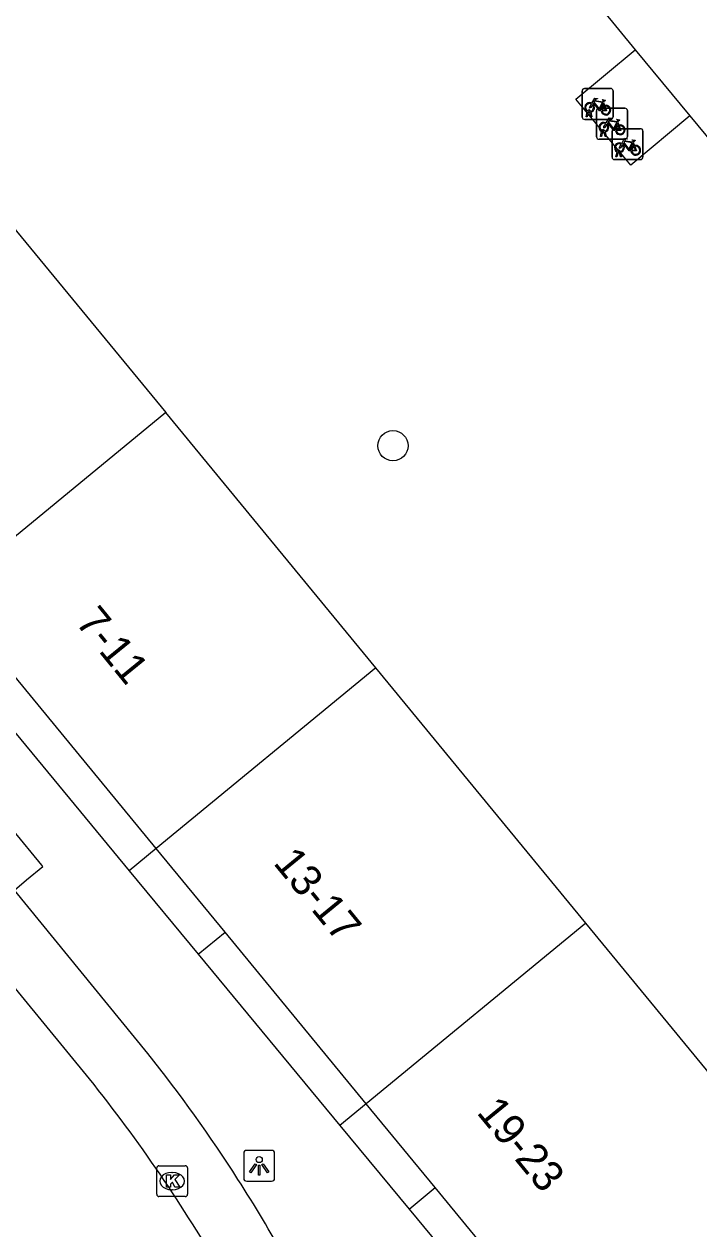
# Model space of a CAD drawing. Extents: x 162347 to 162868, y 381221 to 381813.
# Drawn here: x 162450.01 to 162471.84, y 381680.03 to 381719.03 of the extents above; entities that cross this region are included whole.
import ezdxf

# ---------------------------------------------------------------- set-up
doc = ezdxf.new("R2010")
doc.units = 0
for name, color, linetype in [('IMGEO_Boom', 7, 'Continuous'), ('IMGEO_Fietsenrek', 7, 'Continuous'), ('IMGEO_Kolk', 7, 'Continuous'), ('IMGEO_Lichtpunt', 7, 'Continuous'), ('IMGEO_Pand', 7, 'Continuous'), ('IMGEO_Pand_nummerreeks', 7, 'Continuous'), ('IMGEO_Rijbaan_lokaal_open', 7, 'Continuous'), ('IMGEO_Voetpad_open', 7, 'Continuous')]:
    doc.layers.add(name, color=color, linetype=linetype)

msp = doc.modelspace()

# ---------------------------------------------------------------- linework, layer by layer
at = {"layer": 'IMGEO_Boom'}
msp.add_circle((162461.946, 381705.383), 0.489, dxfattribs=at)
at = {"layer": 'IMGEO_Fietsenrek'}
for p, q in [((162468.067, 381716.021), (162468.067, 381716.862)), ((162468.067, 381716.862), (162468.067, 381716.021)), ((162468.142, 381716.946), (162468.983, 381716.946)), ((162468.983, 381716.946), (162468.142, 381716.946)), ((162469.067, 381716.871), (162469.067, 381716.03)), ((162469.067, 381716.03), (162469.067, 381716.871)), ((162468.754, 381716.495), (162468.79, 381716.4)), ((162468.194, 381716.03), (162468.233, 381716.19)), ((162468.263, 381716.178), (162468.228, 381716.03)), ((162468.305, 381716.202), (162468.304, 381716.206)), ((162468.346, 381716.03), (162468.312, 381716.172)), ((162468.336, 381716.213), (162468.337, 381716.206)), ((162468.344, 381716.176), (162468.379, 381716.03)), ((162468.53, 381715.382), (162468.53, 381716.223)), ((162468.53, 381716.223), (162468.53, 381715.382)), ((162468.605, 381716.307), (162469.446, 381716.307)), ((162469.446, 381716.307), (162468.605, 381716.307)), ((162469.53, 381716.232), (162469.53, 381715.391)), ((162469.53, 381715.391), (162469.53, 381716.232)), ((162468.992, 381715.946), (162468.151, 381715.946)), ((162468.151, 381715.946), (162468.992, 381715.946)), ((162468.228, 381716.03), (162468.194, 381716.03)), ((162468.379, 381716.03), (162468.346, 381716.03)), ((162469.217, 381715.856), (162469.253, 381715.761)), ((162469.455, 381715.307), (162468.614, 381715.307)), ((162468.614, 381715.307), (162469.455, 381715.307)), ((162468.657, 381715.391), (162468.696, 381715.551)), ((162468.691, 381715.391), (162468.657, 381715.391)), ((162468.726, 381715.539), (162468.691, 381715.391)), ((162468.768, 381715.563), (162468.767, 381715.567)), ((162468.809, 381715.391), (162468.775, 381715.533)), ((162468.799, 381715.574), (162468.8, 381715.567)), ((162468.807, 381715.537), (162468.842, 381715.391)), ((162468.842, 381715.391), (162468.809, 381715.391)), ((162469.032, 381714.72), (162469.032, 381715.561)), ((162469.032, 381715.561), (162469.032, 381714.72)), ((162469.107, 381715.645), (162469.948, 381715.645)), ((162469.948, 381715.645), (162469.107, 381715.645)), ((162470.032, 381715.57), (162470.032, 381714.729)), ((162470.032, 381714.729), (162470.032, 381715.57)), ((162469.159, 381714.729), (162469.198, 381714.889)), ((162469.228, 381714.877), (162469.193, 381714.729)), ((162469.27, 381714.901), (162469.269, 381714.905)), ((162469.301, 381714.912), (162469.302, 381714.905)), ((162469.719, 381715.194), (162469.755, 381715.099)), ((162469.957, 381714.645), (162469.116, 381714.645)), ((162469.116, 381714.645), (162469.957, 381714.645)), ((162469.193, 381714.729), (162469.159, 381714.729)), ((162469.311, 381714.729), (162469.277, 381714.871)), ((162469.309, 381714.875), (162469.344, 381714.729)), ((162469.344, 381714.729), (162469.311, 381714.729))]:
    msp.add_line(p, q, dxfattribs=at)
for points in [[(162468.401, 381716.42), (162468.349, 381716.33), (162468.309, 381716.305), (162468.31, 381716.352), (162468.365, 381716.446)], [(162468.38, 381716.472), (162468.475, 381716.636), (162468.561, 381716.622), (162468.563, 381716.613), (162468.507, 381716.602), (162468.48, 381716.557), (162468.736, 381716.516)], [(162468.676, 381716.228), (162468.626, 381716.228), (162468.435, 381716.479), (162468.416, 381716.447)], [(162468.723, 381716.491), (162468.466, 381716.532), (162468.449, 381716.503), (162468.616, 381716.283), (162468.723, 381716.491)], [(162468.771, 381716.393), (162468.741, 381716.47), (162468.632, 381716.252), (162468.675, 381716.252)], [(162468.736, 381716.516), (162468.761, 381716.565), (162468.755, 381716.569), (162468.732, 381716.573), (162468.72, 381716.58), (162468.719, 381716.583), (162468.721, 381716.588), (162468.816, 381716.573), (162468.818, 381716.563), (162468.808, 381716.55), (162468.796, 381716.544), (162468.782, 381716.55), (162468.754, 381716.495)], [(162468.705, 381716.252), (162468.825, 381716.251), (162468.781, 381716.365)], [(162468.801, 381716.372), (162468.856, 381716.227), (162468.706, 381716.227)], [(162468.864, 381715.781), (162468.812, 381715.691), (162468.772, 381715.666), (162468.773, 381715.713), (162468.828, 381715.807)], [(162468.843, 381715.833), (162468.938, 381715.997), (162469.024, 381715.983), (162469.026, 381715.974), (162468.97, 381715.963), (162468.943, 381715.918), (162469.199, 381715.877)], [(162469.139, 381715.589), (162469.089, 381715.589), (162468.898, 381715.84), (162468.879, 381715.808)], [(162469.186, 381715.852), (162468.929, 381715.893), (162468.912, 381715.864), (162469.079, 381715.644), (162469.186, 381715.852)], [(162469.234, 381715.754), (162469.204, 381715.831), (162469.095, 381715.613), (162469.138, 381715.613)], [(162469.168, 381715.613), (162469.288, 381715.612), (162469.244, 381715.726)], [(162469.264, 381715.733), (162469.319, 381715.588), (162469.169, 381715.588)], [(162469.199, 381715.877), (162469.224, 381715.926), (162469.218, 381715.93), (162469.195, 381715.934), (162469.183, 381715.941), (162469.182, 381715.944), (162469.184, 381715.949), (162469.279, 381715.934), (162469.281, 381715.924), (162469.271, 381715.911), (162469.259, 381715.905), (162469.245, 381715.911), (162469.217, 381715.856)], [(162469.345, 381715.171), (162469.44, 381715.335), (162469.526, 381715.321), (162469.528, 381715.312), (162469.472, 381715.301), (162469.445, 381715.256), (162469.701, 381715.215)], [(162469.701, 381715.215), (162469.726, 381715.264), (162469.72, 381715.268), (162469.697, 381715.272), (162469.685, 381715.279), (162469.684, 381715.282), (162469.686, 381715.287), (162469.781, 381715.272), (162469.783, 381715.262), (162469.773, 381715.249), (162469.761, 381715.243), (162469.747, 381715.249), (162469.719, 381715.194)], [(162469.366, 381715.119), (162469.314, 381715.029), (162469.274, 381715.004), (162469.275, 381715.051), (162469.33, 381715.145)], [(162469.641, 381714.927), (162469.591, 381714.927), (162469.4, 381715.178), (162469.381, 381715.146)], [(162469.688, 381715.19), (162469.431, 381715.231), (162469.414, 381715.202), (162469.581, 381714.982), (162469.688, 381715.19)], [(162469.736, 381715.092), (162469.706, 381715.169), (162469.597, 381714.951), (162469.64, 381714.951)], [(162469.67, 381714.951), (162469.79, 381714.95), (162469.746, 381715.064)], [(162469.766, 381715.071), (162469.821, 381714.926), (162469.671, 381714.926)]]:
    msp.add_lwpolyline(points, dxfattribs=at)
for centre, radius, start, end in [((162468.145, 381716.868), 0.0779, 92.4484, 184.2845), ((162468.145, 381716.868), 0.0779, 92.4484, 184.2845), ((162468.989, 381716.868), 0.0779, 2.4484, 94.2845), ((162468.989, 381716.868), 0.0779, 2.4484, 94.2845), ((162468.307, 381716.331), 0.159, 62.6766, 242.1369), ((162468.307, 381716.331), 0.129, 63.3192, 238.903), ((162468.307, 381716.331), 0.159, 283.5766, 46.6042), ((162468.287, 381716.202), 0.0499, 12.8025, 158.6934), ((162468.307, 381716.331), 0.159, 253.9967, 271.7867), ((162468.287, 381716.202), 0.0174, 12.8025, 163.4502), ((162468.307, 381716.331), 0.129, 253.415, 269.0204), ((162468.307, 381716.331), 0.129, 283.6043, 43.4302), ((162468.608, 381716.229), 0.0779, 92.4484, 184.2845), ((162468.608, 381716.229), 0.0779, 92.4484, 184.2845), ((162468.834, 381716.247), 0.159, 113.3408, 178.3217), ((162468.834, 381716.247), 0.159, 187.0065, 105.7708), ((162468.834, 381716.247), 0.129, 113.923, 177.9556), ((162468.834, 381716.247), 0.129, 188.6715, 104.5883), ((162469.452, 381716.229), 0.0779, 2.4484, 94.2845), ((162469.452, 381716.229), 0.0779, 2.4484, 94.2845), ((162468.145, 381716.024), 0.0779, 182.4484, 274.2845), ((162468.145, 381716.024), 0.0779, 182.4484, 274.2845), ((162468.77, 381715.692), 0.159, 62.6766, 242.1369), ((162468.77, 381715.692), 0.129, 63.3192, 238.903), ((162468.77, 381715.692), 0.129, 283.6043, 43.4302), ((162468.77, 381715.692), 0.159, 283.5766, 46.6042), ((162468.989, 381716.024), 0.0779, 272.4484, 4.2845), ((162468.989, 381716.024), 0.0779, 272.4484, 4.2845), ((162469.297, 381715.608), 0.159, 113.3408, 178.3217), ((162469.297, 381715.608), 0.159, 187.0065, 105.7708), ((162469.297, 381715.608), 0.129, 113.923, 177.9556), ((162469.297, 381715.608), 0.129, 188.6715, 104.5883), ((162468.608, 381715.385), 0.0779, 182.4484, 274.2845), ((162468.608, 381715.385), 0.0779, 182.4484, 274.2845), ((162468.75, 381715.563), 0.0499, 12.8025, 158.6934), ((162468.77, 381715.692), 0.159, 253.9967, 271.7867), ((162468.75, 381715.563), 0.0174, 12.8025, 163.4502), ((162468.77, 381715.692), 0.129, 253.415, 269.0204), ((162469.11, 381715.567), 0.0779, 92.4484, 184.2845), ((162469.11, 381715.567), 0.0779, 92.4484, 184.2845), ((162469.452, 381715.385), 0.0779, 272.4484, 4.2845), ((162469.452, 381715.385), 0.0779, 272.4484, 4.2845), ((162469.954, 381715.567), 0.0779, 2.4484, 94.2845), ((162469.954, 381715.567), 0.0779, 2.4484, 94.2845), ((162469.272, 381715.03), 0.159, 62.6766, 242.1369), ((162469.272, 381715.03), 0.129, 63.3192, 238.903), ((162469.252, 381714.901), 0.0499, 12.8025, 158.6934), ((162469.272, 381715.03), 0.159, 253.9967, 271.7867), ((162469.252, 381714.901), 0.0174, 12.8025, 163.4502), ((162469.272, 381715.03), 0.129, 253.415, 269.0204), ((162469.272, 381715.03), 0.129, 283.6043, 43.4302), ((162469.272, 381715.03), 0.159, 283.5766, 46.6042), ((162469.799, 381714.946), 0.159, 113.3408, 178.3217), ((162469.799, 381714.946), 0.159, 187.0065, 105.7708), ((162469.799, 381714.946), 0.129, 113.923, 177.9556), ((162469.799, 381714.946), 0.129, 188.6715, 104.5883), ((162469.11, 381714.723), 0.0779, 182.4484, 274.2845), ((162469.11, 381714.723), 0.0779, 182.4484, 274.2845), ((162469.954, 381714.723), 0.0779, 272.4484, 4.2845), ((162469.954, 381714.723), 0.0779, 272.4484, 4.2845)]:
    msp.add_arc(centre, radius, start, end, dxfattribs=at)
at = {"layer": 'IMGEO_Kolk'}
for p, q in [((162454.301, 381681.153), (162454.301, 381682.005)), ((162454.376, 381682.079), (162455.228, 381682.079)), ((162454.789, 381681.859), (162454.814, 381681.859)), ((162455.302, 381682.005), (162455.302, 381681.153)), ((162455.228, 381681.079), (162454.376, 381681.079)), ((162454.812, 381681.299), (162454.787, 381681.299))]:
    msp.add_line(p, q, dxfattribs=at)
for points in [[(162454.301, 381681.153), (162454.301, 381682.005)], [(162454.376, 381682.079), (162455.228, 381682.079)], [(162454.622, 381681.779), (162454.745, 381681.779), (162454.745, 381681.628), (162454.875, 381681.779), (162455.039, 381681.779), (162454.893, 381681.628), (162455.046, 381681.379), (162454.894, 381681.379), (162454.809, 381681.543), (162454.745, 381681.476), (162454.745, 381681.379), (162454.622, 381681.379), (162454.622, 381681.779)], [(162455.302, 381682.005), (162455.302, 381681.153)], [(162455.228, 381681.079), (162454.376, 381681.079)]]:
    msp.add_lwpolyline(points, dxfattribs=at)
for centre, start, end in [((162454.378, 381682.003), 91.552, 178.448), ((162454.378, 381682.003), 91.552, 178.448), ((162455.226, 381682.003), 1.552, 88.448), ((162455.226, 381682.003), 1.552, 88.448), ((162454.378, 381681.155), 181.552, 268.448), ((162454.378, 381681.155), 181.552, 268.448), ((162455.226, 381681.155), 271.552, 358.448), ((162455.226, 381681.155), 271.552, 358.448)]:
    msp.add_arc(centre, 0.0765, start, end, dxfattribs=at)
for centre, major_axis, ratio, start_param, end_param in [((162454.788, 381681.579), (-0.387, 0.002), 0.722429, 4.712389, 7.853982), ((162454.813, 381681.579), (-0.39, 0.002), 0.717154, 1.570796, 4.712389)]:
    msp.add_ellipse(centre, major_axis=major_axis, ratio=ratio, start_param=start_param, end_param=end_param, dxfattribs=at)
at = {"layer": 'IMGEO_Lichtpunt'}
for p, q in [((162458.021, 381682.574), (162457.213, 381682.574)), ((162458.021, 381682.574), (162457.213, 381682.574)), ((162457.119, 381682.479), (162457.119, 381681.672)), ((162457.119, 381682.479), (162457.119, 381681.672)), ((162458.115, 381681.672), (162458.115, 381682.479)), ((162458.115, 381681.672), (162458.115, 381682.479)), ((162457.213, 381681.578), (162458.021, 381681.578)), ((162457.213, 381681.578), (162458.021, 381681.578))]:
    msp.add_line(p, q, dxfattribs=at)
for points in [[(162457.493, 381682.143), (162457.532, 381682.115), (162457.344, 381681.853), (162457.306, 381681.88), (162457.493, 381682.143)], [(162457.705, 381682.115), (162457.743, 381682.142), (162457.93, 381681.88), (162457.891, 381681.852), (162457.705, 381682.115)], [(162457.595, 381682.095), (162457.642, 381682.095), (162457.642, 381681.773), (162457.595, 381681.773), (162457.595, 381682.095)]]:
    msp.add_lwpolyline(points, dxfattribs=at)
msp.add_circle((162457.618, 381682.277), 0.0994, dxfattribs=at)
for centre, start, end in [((162457.213, 381682.479), 90, 180), ((162457.213, 381682.479), 90, 180), ((162458.021, 381682.479), 0, 90), ((162458.021, 381682.479), 0, 90), ((162457.213, 381681.672), 180, 270), ((162457.213, 381681.672), 180, 270), ((162458.021, 381681.672), 270, 0), ((162458.021, 381681.672), 270, 360)]:
    msp.add_arc(centre, 0.0946, start, end, dxfattribs=at)
at = {"layer": 'IMGEO_Pand'}
for points in [[(162447.798, 381714.718), (162454.595, 381706.454)], [(162454.595, 381706.454), (162447.491, 381700.611)], [(162461.391, 381698.19), (162454.595, 381706.454)], [(162461.391, 381698.19), (162454.287, 381692.347)], [(162468.188, 381689.926), (162461.391, 381698.19)], [(162454.287, 381692.347), (162449.721, 381697.9)], [(162456.517, 381689.636), (162454.287, 381692.347)], [(162468.188, 381689.926), (162461.084, 381684.083)], [(162474.743, 381681.955), (162468.188, 381689.926)], [(162461.084, 381684.083), (162456.517, 381689.636)], [(162463.314, 381681.372), (162461.084, 381684.083)], [(162467.639, 381676.112), (162463.314, 381681.372)]]:
    msp.add_lwpolyline(points, dxfattribs=at)
at = {"layer": 'IMGEO_Rijbaan_lokaal_open'}
msp.add_lwpolyline([(162452.127, 381684.891), (162445.52, 381692.954)], dxfattribs=at)
msp.add_arc((162411.785, 381652.7), 51.611, 30.0534, 38.5887, dxfattribs=at)
at = {"layer": 'IMGEO_Voetpad_open'}
for points in [[(162463.314, 381726.102), (162469.783, 381718.202)], [(162471.549, 381716.061), (162469.643, 381714.467), (162467.863, 381716.602), (162469.783, 381718.202)], [(162469.783, 381718.202), (162471.549, 381716.061)], [(162471.549, 381716.061), (162476.506, 381710.061)], [(162448.828, 381697.166), (162453.41, 381691.626)], [(162449.697, 381691), (162450.093, 381691.327), (162450.623, 381691.763), (162450.589, 381691.804), (162447.758, 381695.241), (162446.171, 381693.919), (162445.318, 381693.193)], [(162454.287, 381692.347), (162453.41, 381691.626)], [(162453.41, 381691.626), (162455.647, 381688.921)], [(162454.017, 381685.708), (162449.697, 381691)], [(162455.647, 381688.921), (162456.517, 381689.636)], [(162455.647, 381688.921), (162460.23, 381683.381)], [(162461.084, 381684.083), (162460.23, 381683.381)], [(162460.23, 381683.381), (162462.467, 381680.676)], [(162462.467, 381680.676), (162463.314, 381681.372)], [(162462.467, 381680.676), (162466.808, 381675.428)]]:
    msp.add_lwpolyline(points, dxfattribs=at)
for centre, radius, start, end in [((162415.813, 381655.28), 48.841, 32.6589, 38.5362), ((162416.044, 381655.409), 48.576, 25.5992, 32.6771)]:
    msp.add_arc(centre, radius, start, end, dxfattribs=at)

# ---------------------------------------------------------------- texts
at = {"layer": 'IMGEO_Pand_nummerreeks'}
for s, rotation, p in [('7-11', 309.1729, (162451.648, 381699.658)), ('13-17', 309.3219, (162458.048, 381691.869)), ('19-23', 309.3391, (162464.627, 381683.794))]:
    msp.add_text(s, height=1, rotation=rotation, dxfattribs=at).set_placement(p)

doc.saveas('drawing.dxf')
